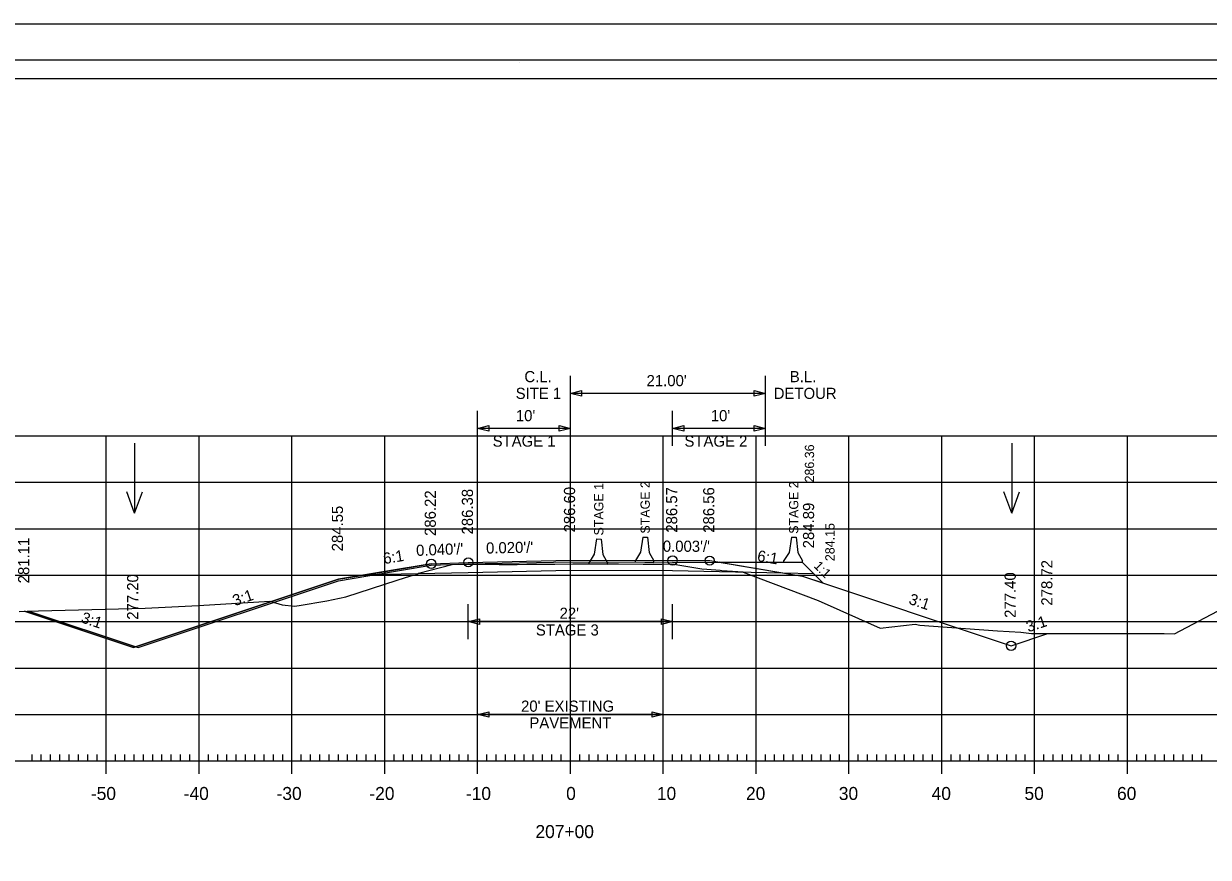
# Model space of a CAD drawing. Extents: x 1368713 to 1370673, y 380279 to 380950.
# Drawn here: x 1370450.7 to 1370578.3, y 380647.4 to 380737.1 of the extents above; entities that cross this region are included whole.
import ezdxf

# ---------------------------------------------------------------- set-up
doc = ezdxf.new("R2010")
doc.units = 0
for name, color, linetype in [('R_Alt Surface', 7, 'Continuous'), ('R_Axis', 7, 'Continuous'), ('R_Axis Annot', 7, 'Continuous'), ('R_Border', 7, 'Continuous'), ('R_CONC BARRIER', 7, 'Continuous'), ('R_Exist Surface', 7, 'Continuous'), ('R_Fin Surface', 7, 'Continuous'), ('R_Grid', 7, 'Continuous'), ('R_No Plot', 7, 'Continuous'), ('R_ROW Annot', 7, 'Continuous'), ('R_Stage 3 EW', 7, 'Continuous'), ('R_Water Annot', 7, 'Continuous'), ('R_Xsect Elev', 7, 'Continuous'), ('R_Xsect Slope', 7, 'Continuous')]:
    doc.layers.add(name, color=color, linetype=linetype)

msp = doc.modelspace()

# ---------------------------------------------------------------- linework, layer by layer
at = {"layer": 'R_Alt Surface'}
msp.add_line((1370532.48, 380678), (1370535.81, 380677.93), dxfattribs=at)
for points in [[(1370451.29, 380673.88), (1370463.07, 380669.95), (1370484.63, 380677.14), (1370487.79, 380677.67), (1370494.63, 380678.81), (1370498.63, 380678.97), (1370509.63, 380679.19), (1370520.63, 380679.15), (1370534.63, 380679.11), (1370535.98, 380677.76), (1370536.83, 380676.91)], [(1370494.63, 380678.97), (1370484.63, 380677.31)], [(1370524.63, 380679.31), (1370534.63, 380677.64)], [(1370487.79, 380677.83), (1370498.63, 380678.05), (1370509.63, 380678.27), (1370520.63, 380678.24), (1370532.48, 380678)], [(1370484.63, 380677.31), (1370462.57, 380669.95)], [(1370534.63, 380677.64), (1370557.1, 380670.15)], [(1370462.57, 380669.95), (1370462.57, 380669.95), (1370450.83, 380673.87)], [(1370557.1, 380670.15), (1370557.1, 380670.15), (1370561.05, 380671.47)]]:
    msp.add_lwpolyline(points, dxfattribs=at)
at = {"layer": 'R_Axis'}
for p, q in [((1370459.63, 380656.35), (1370459.63, 380659.15)), ((1370469.63, 380656.35), (1370469.63, 380659.15)), ((1370479.63, 380656.35), (1370479.63, 380659.15)), ((1370489.63, 380656.35), (1370489.63, 380659.15)), ((1370499.63, 380656.35), (1370499.63, 380659.15)), ((1370509.63, 380656.35), (1370509.63, 380659.15)), ((1370519.63, 380656.35), (1370519.63, 380659.15)), ((1370529.63, 380656.35), (1370529.63, 380659.15)), ((1370539.63, 380656.35), (1370539.63, 380659.15)), ((1370549.63, 380656.35), (1370549.63, 380659.15)), ((1370559.63, 380656.35), (1370559.63, 380659.15)), ((1370569.63, 380656.35), (1370569.63, 380659.15)), ((1370369.63, 380657.75), (1370649.63, 380657.75)), ((1370451.63, 380657.75), (1370451.63, 380658.45)), ((1370452.63, 380657.75), (1370452.63, 380658.45)), ((1370453.63, 380657.75), (1370453.63, 380658.45)), ((1370454.63, 380657.75), (1370454.63, 380658.45)), ((1370455.63, 380657.75), (1370455.63, 380658.45)), ((1370456.63, 380657.75), (1370456.63, 380658.45)), ((1370457.63, 380657.75), (1370457.63, 380658.45)), ((1370458.63, 380657.75), (1370458.63, 380658.45)), ((1370460.63, 380657.75), (1370460.63, 380658.45)), ((1370461.63, 380657.75), (1370461.63, 380658.45)), ((1370462.63, 380657.75), (1370462.63, 380658.45)), ((1370463.63, 380657.75), (1370463.63, 380658.45)), ((1370464.63, 380657.75), (1370464.63, 380658.45)), ((1370465.63, 380657.75), (1370465.63, 380658.45)), ((1370466.63, 380657.75), (1370466.63, 380658.45)), ((1370467.63, 380657.75), (1370467.63, 380658.45)), ((1370468.63, 380657.75), (1370468.63, 380658.45)), ((1370470.63, 380657.75), (1370470.63, 380658.45)), ((1370471.63, 380657.75), (1370471.63, 380658.45)), ((1370472.63, 380657.75), (1370472.63, 380658.45)), ((1370473.63, 380657.75), (1370473.63, 380658.45)), ((1370474.63, 380657.75), (1370474.63, 380658.45)), ((1370475.63, 380657.75), (1370475.63, 380658.45)), ((1370476.63, 380657.75), (1370476.63, 380658.45)), ((1370477.63, 380657.75), (1370477.63, 380658.45)), ((1370478.63, 380657.75), (1370478.63, 380658.45)), ((1370480.63, 380657.75), (1370480.63, 380658.45)), ((1370481.63, 380657.75), (1370481.63, 380658.45)), ((1370482.63, 380657.75), (1370482.63, 380658.45)), ((1370483.63, 380657.75), (1370483.63, 380658.45)), ((1370484.63, 380657.75), (1370484.63, 380658.45)), ((1370485.63, 380657.75), (1370485.63, 380658.45)), ((1370486.63, 380657.75), (1370486.63, 380658.45)), ((1370487.63, 380657.75), (1370487.63, 380658.45)), ((1370488.63, 380657.75), (1370488.63, 380658.45)), ((1370490.63, 380657.75), (1370490.63, 380658.45)), ((1370491.63, 380657.75), (1370491.63, 380658.45)), ((1370492.63, 380657.75), (1370492.63, 380658.45)), ((1370493.63, 380657.75), (1370493.63, 380658.45)), ((1370494.63, 380657.75), (1370494.63, 380658.45)), ((1370495.63, 380657.75), (1370495.63, 380658.45)), ((1370496.63, 380657.75), (1370496.63, 380658.45)), ((1370497.63, 380657.75), (1370497.63, 380658.45)), ((1370498.63, 380657.75), (1370498.63, 380658.45)), ((1370500.63, 380657.75), (1370500.63, 380658.45)), ((1370501.63, 380657.75), (1370501.63, 380658.45)), ((1370502.63, 380657.75), (1370502.63, 380658.45)), ((1370503.63, 380657.75), (1370503.63, 380658.45)), ((1370504.63, 380657.75), (1370504.63, 380658.45)), ((1370505.63, 380657.75), (1370505.63, 380658.45)), ((1370506.63, 380657.75), (1370506.63, 380658.45)), ((1370507.63, 380657.75), (1370507.63, 380658.45)), ((1370508.63, 380657.75), (1370508.63, 380658.45)), ((1370510.63, 380657.75), (1370510.63, 380658.45)), ((1370511.63, 380657.75), (1370511.63, 380658.45)), ((1370512.63, 380657.75), (1370512.63, 380658.45)), ((1370513.63, 380657.75), (1370513.63, 380658.45)), ((1370514.63, 380657.75), (1370514.63, 380658.45)), ((1370515.63, 380657.75), (1370515.63, 380658.45)), ((1370516.63, 380657.75), (1370516.63, 380658.45)), ((1370517.63, 380657.75), (1370517.63, 380658.45)), ((1370518.63, 380657.75), (1370518.63, 380658.45)), ((1370520.63, 380657.75), (1370520.63, 380658.45)), ((1370521.63, 380657.75), (1370521.63, 380658.45)), ((1370522.63, 380657.75), (1370522.63, 380658.45)), ((1370523.63, 380657.75), (1370523.63, 380658.45)), ((1370524.63, 380657.75), (1370524.63, 380658.45)), ((1370525.63, 380657.75), (1370525.63, 380658.45)), ((1370526.63, 380657.75), (1370526.63, 380658.45)), ((1370527.63, 380657.75), (1370527.63, 380658.45)), ((1370528.63, 380657.75), (1370528.63, 380658.45)), ((1370530.63, 380657.75), (1370530.63, 380658.45)), ((1370531.63, 380657.75), (1370531.63, 380658.45)), ((1370532.63, 380657.75), (1370532.63, 380658.45)), ((1370533.63, 380657.75), (1370533.63, 380658.45)), ((1370534.63, 380657.75), (1370534.63, 380658.45)), ((1370535.63, 380657.75), (1370535.63, 380658.45)), ((1370536.63, 380657.75), (1370536.63, 380658.45)), ((1370537.63, 380657.75), (1370537.63, 380658.45)), ((1370538.63, 380657.75), (1370538.63, 380658.45)), ((1370540.63, 380657.75), (1370540.63, 380658.45)), ((1370541.63, 380657.75), (1370541.63, 380658.45)), ((1370542.63, 380657.75), (1370542.63, 380658.45)), ((1370543.63, 380657.75), (1370543.63, 380658.45)), ((1370544.63, 380657.75), (1370544.63, 380658.45)), ((1370545.63, 380657.75), (1370545.63, 380658.45)), ((1370546.63, 380657.75), (1370546.63, 380658.45)), ((1370547.63, 380657.75), (1370547.63, 380658.45)), ((1370548.63, 380657.75), (1370548.63, 380658.45)), ((1370550.63, 380657.75), (1370550.63, 380658.45)), ((1370551.63, 380657.75), (1370551.63, 380658.45)), ((1370552.63, 380657.75), (1370552.63, 380658.45)), ((1370553.63, 380657.75), (1370553.63, 380658.45)), ((1370554.63, 380657.75), (1370554.63, 380658.45)), ((1370555.63, 380657.75), (1370555.63, 380658.45)), ((1370556.63, 380657.75), (1370556.63, 380658.45)), ((1370557.63, 380657.75), (1370557.63, 380658.45)), ((1370558.63, 380657.75), (1370558.63, 380658.45)), ((1370560.63, 380657.75), (1370560.63, 380658.45)), ((1370561.63, 380657.75), (1370561.63, 380658.45)), ((1370562.63, 380657.75), (1370562.63, 380658.45)), ((1370563.63, 380657.75), (1370563.63, 380658.45)), ((1370564.63, 380657.75), (1370564.63, 380658.45)), ((1370565.63, 380657.75), (1370565.63, 380658.45)), ((1370566.63, 380657.75), (1370566.63, 380658.45)), ((1370567.63, 380657.75), (1370567.63, 380658.45)), ((1370568.63, 380657.75), (1370568.63, 380658.45)), ((1370570.63, 380657.75), (1370570.63, 380658.45)), ((1370571.63, 380657.75), (1370571.63, 380658.45)), ((1370572.63, 380657.75), (1370572.63, 380658.45)), ((1370573.63, 380657.75), (1370573.63, 380658.45)), ((1370574.63, 380657.75), (1370574.63, 380658.45)), ((1370575.63, 380657.75), (1370575.63, 380658.45)), ((1370576.63, 380657.75), (1370576.63, 380658.45)), ((1370577.63, 380657.75), (1370577.63, 380658.45))]:
    msp.add_line(p, q, dxfattribs=at)
at = {"layer": 'R_Border'}
for p, q in [((1370351.63, 380733.21), (1370667.81, 380733.21)), ((1370504.15, 380732.95), (1370504.15, 380732.95)), ((1370504.15, 380732.95), (1370504.15, 380732.95))]:
    msp.add_line(p, q, dxfattribs=at)
at = {"layer": 'R_CONC BARRIER'}
for p, q in [((1370512.43, 380681.65), (1370512.93, 380681.64)), ((1370517.43, 380681.85), (1370517.93, 380681.84)), ((1370533.43, 380681.84), (1370533.93, 380681.83)), ((1370511.63, 380678.97), (1370511.63, 380679.13)), ((1370511.63, 380678.97), (1370513.63, 380678.93)), ((1370513.63, 380678.93), (1370513.63, 380679.09)), ((1370516.63, 380679.17), (1370516.63, 380679.33)), ((1370516.63, 380679.17), (1370518.63, 380679.13)), ((1370518.63, 380679.13), (1370518.63, 380679.29)), ((1370532.63, 380679.15), (1370532.63, 380679.32)), ((1370532.63, 380679.15), (1370534.63, 380679.11)), ((1370534.63, 380679.11), (1370534.63, 380679.28))]:
    msp.add_line(p, q, dxfattribs=at)
for points in [[(1370512.43, 380681.65), (1370512.18, 380680.01), (1370511.63, 380679.13)], [(1370512.93, 380681.64), (1370513.12, 380679.99), (1370513.63, 380679.09)], [(1370517.43, 380681.85), (1370517.18, 380680.21), (1370516.63, 380679.33)], [(1370517.93, 380681.84), (1370518.12, 380680.19), (1370518.63, 380679.29)], [(1370533.43, 380681.84), (1370533.18, 380680.2), (1370532.63, 380679.32)], [(1370533.93, 380681.83), (1370534.12, 380680.18), (1370534.63, 380679.28)]]:
    msp.add_lwpolyline(points, dxfattribs=at)
at = {"layer": 'R_Exist Surface'}
msp.add_lwpolyline([(1370450.25, 380673.85), (1370451.1, 380673.87), (1370452.33, 380673.91), (1370463.81, 380674.18), (1370469.57, 380674.47), (1370477.24, 380674.96), (1370478.56, 380674.57), (1370479.91, 380674.42), (1370480.4, 380674.48), (1370483.39, 380674.97), (1370485.42, 380675.42), (1370490.97, 380677.2), (1370492.42, 380677.68), (1370493.08, 380677.83), (1370493.28, 380677.95), (1370496.88, 380678.91), (1370499.66, 380678.93), (1370501.94, 380678.88), (1370503.88, 380678.9), (1370504.95, 380678.92), (1370506.88, 380678.95), (1370507.95, 380678.95), (1370509.88, 380678.96), (1370510.95, 380678.96), (1370512.88, 380678.97), (1370514.79, 380678.97), (1370517.48, 380678.94), (1370519.48, 380678.95), (1370520.56, 380678.96), (1370523.8, 380678.42), (1370524.33, 380678.39), (1370525.77, 380678.29), (1370525.95, 380678.24), (1370528.22, 380678.09), (1370528.24, 380678.08), (1370536.33, 380675.02), (1370542.99, 380672.04), (1370546.75, 380672.48), (1370547.27, 380672.36), (1370555.63, 380671.74), (1370558.15, 380671.63), (1370559.31, 380671.47), (1370565.36, 380671.47), (1370573.58, 380671.47), (1370574.72, 380671.42), (1370580.02, 380674.23)], dxfattribs=at)
at = {"layer": 'R_Fin Surface'}
for points in [[(1370450.83, 380673.87), (1370462.57, 380669.95), (1370484.63, 380677.31), (1370487.79, 380677.83), (1370494.63, 380678.97), (1370498.63, 380679.13), (1370509.63, 380679.35), (1370520.63, 380679.32), (1370524.63, 380679.31), (1370532.48, 380678), (1370534.63, 380677.64), (1370557.1, 380670.15), (1370561.05, 380671.47)], [(1370494.63, 380678.97), (1370498.63, 380679.13), (1370509.63, 380679.35), (1370520.63, 380679.32), (1370524.63, 380679.31)]]:
    msp.add_lwpolyline(points, dxfattribs=at)
at = {"layer": 'R_Grid'}
for p, q in [((1370369.63, 380692.75), (1370649.63, 380692.75)), ((1370459.63, 380657.75), (1370459.63, 380692.75)), ((1370469.63, 380657.75), (1370469.63, 380692.75)), ((1370479.63, 380657.75), (1370479.63, 380692.75)), ((1370489.63, 380657.75), (1370489.63, 380692.75)), ((1370499.63, 380657.75), (1370499.63, 380692.75)), ((1370509.63, 380657.75), (1370509.63, 380692.75)), ((1370519.63, 380657.75), (1370519.63, 380692.75)), ((1370529.63, 380657.75), (1370529.63, 380692.75)), ((1370539.63, 380657.75), (1370539.63, 380692.75)), ((1370549.63, 380657.75), (1370549.63, 380692.75)), ((1370559.63, 380657.75), (1370559.63, 380692.75)), ((1370569.63, 380657.75), (1370569.63, 380692.75)), ((1370369.63, 380687.75), (1370649.63, 380687.75)), ((1370369.63, 380682.75), (1370649.63, 380682.75)), ((1370369.63, 380677.75), (1370649.63, 380677.75)), ((1370369.63, 380672.75), (1370649.63, 380672.75)), ((1370369.63, 380667.75), (1370649.63, 380667.75)), ((1370369.63, 380662.75), (1370649.63, 380662.75)), ((1370369.63, 380657.75), (1370649.63, 380657.75))]:
    msp.add_line(p, q, dxfattribs=at)
at = {"layer": 'R_No Plot'}
for points in [[(1370339.22, 380737.11), (1370672.56, 380737.11), (1370672.56, 380523.77), (1370339.22, 380523.77)], [(1370665.81, 380632.48), (1370353.63, 380632.48), (1370353.63, 380731.21), (1370603.17, 380731.21), (1370603.17, 380721.33), (1370620.71, 380721.33), (1370644.81, 380721.33), (1370644.81, 380699), (1370665.81, 380699)], [(1370353.63, 380731.21), (1370603.17, 380731.21), (1370603.17, 380721.33), (1370620.71, 380721.33), (1370644.81, 380721.33), (1370644.81, 380699), (1370665.81, 380699), (1370665.81, 380529.75), (1370353.63, 380529.75)]]:
    msp.add_lwpolyline(points, close=True, dxfattribs=at)
for centre in [(1370494.63, 380678.97), (1370494.63, 380678.97), (1370498.63, 380679.13), (1370498.63, 380679.13), (1370520.63, 380679.32), (1370520.63, 380679.32), (1370524.63, 380679.31), (1370524.63, 380679.31), (1370557.1, 380670.15), (1370557.1, 380670.15)]:
    msp.add_circle(centre, 0.5, dxfattribs=at)
at = {"layer": 'R_ROW Annot'}
for p, q in [((1370509.63, 380695.44), (1370509.63, 380699.21)), ((1370530.63, 380695.44), (1370530.63, 380699.21)), ((1370530.63, 380697.32), (1370509.63, 380697.32)), ((1370499.63, 380691.67), (1370499.63, 380695.44)), ((1370509.63, 380691.67), (1370509.63, 380695.44)), ((1370520.63, 380691.67), (1370520.63, 380695.44)), ((1370530.63, 380691.67), (1370530.63, 380695.44)), ((1370509.63, 380693.55), (1370499.63, 380693.55)), ((1370530.63, 380693.55), (1370520.63, 380693.55)), ((1370498.63, 380670.87), (1370498.63, 380674.64)), ((1370520.63, 380670.87), (1370520.63, 380674.64)), ((1370520.63, 380672.75), (1370498.63, 380672.75)), ((1370499.63, 380660.87), (1370499.63, 380664.64)), ((1370519.63, 380660.87), (1370519.63, 380664.64)), ((1370519.63, 380662.75), (1370499.63, 380662.75))]:
    msp.add_line(p, q, dxfattribs=at)
for points in [[(1370510.83, 380697.02), (1370509.63, 380697.32), (1370510.83, 380697.62)], [(1370529.43, 380697.62), (1370530.63, 380697.32), (1370529.43, 380697.02)], [(1370500.83, 380693.25), (1370499.63, 380693.55), (1370500.83, 380693.85)], [(1370508.43, 380693.85), (1370509.63, 380693.55), (1370508.43, 380693.25)], [(1370521.83, 380693.25), (1370520.63, 380693.55), (1370521.83, 380693.85)], [(1370529.43, 380693.85), (1370530.63, 380693.55), (1370529.43, 380693.25)], [(1370499.83, 380672.45), (1370498.63, 380672.75), (1370499.83, 380673.05)], [(1370519.43, 380673.05), (1370520.63, 380672.75), (1370519.43, 380672.45)], [(1370500.83, 380662.45), (1370499.63, 380662.75), (1370500.83, 380663.05)], [(1370518.43, 380663.05), (1370519.63, 380662.75), (1370518.43, 380662.45)]]:
    msp.add_lwpolyline(points, close=True, dxfattribs=at)
at = {"layer": 'R_Stage 3 EW'}
for p, q in [((1370534.63, 380679.11), (1370525.65, 380679.14)), ((1370525.65, 380679.14), (1370532.48, 380678)), ((1370536.83, 380676.91), (1370534.63, 380679.11)), ((1370532.48, 380678), (1370534.63, 380677.64)), ((1370534.63, 380677.64), (1370536.83, 380676.91))]:
    msp.add_line(p, q, dxfattribs=at)
at = {"layer": 'R_Water Annot'}
for p, q in [((1370462.68, 380691.95), (1370462.68, 380684.41)), ((1370557.17, 380691.95), (1370557.17, 380684.41)), ((1370462.68, 380684.41), (1370461.84, 380686.72)), ((1370462.68, 380684.41), (1370463.52, 380686.72)), ((1370557.17, 380684.41), (1370556.33, 380686.72)), ((1370557.17, 380684.41), (1370558.01, 380686.72))]:
    msp.add_line(p, q, dxfattribs=at)

# ---------------------------------------------------------------- texts
at = {"layer": 'R_Axis Annot'}
for s, p in [('-50', (1370457.97, 380653.55)), ('-40', (1370467.97, 380653.55)), ('-30', (1370477.97, 380653.55)), ('-20', (1370487.97, 380653.55)), ('-10', (1370498.37, 380653.55)), ('0', (1370509.17, 380653.55)), ('10', (1370518.94, 380653.55)), ('20', (1370528.54, 380653.55)), ('30', (1370538.54, 380653.55)), ('40', (1370548.54, 380653.55)), ('50', (1370558.54, 380653.55)), ('60', (1370568.51, 380653.55)), ('207+00', (1370505.86, 380649.45))]:
    msp.add_text(s, height=1.4, dxfattribs=at).set_placement(p)
at = {"layer": 'R_CONC BARRIER'}
for s, p in [(' STAGE 1', (1370513.18, 380681.65)), (' STAGE 2', (1370518.18, 380681.85)), (' STAGE 2', (1370534.18, 380681.83))]:
    msp.add_text(s, height=1, rotation=90, dxfattribs=at).set_placement(p)
at = {"layer": 'R_ROW Annot'}
for s, p in [('C.L.', (1370504.67, 380698.52)), ('B.L.', (1370533.26, 380698.52)), ("21.00'", (1370517.83, 380698.09)), ('SITE 1', (1370503.73, 380696.72)), ('DETOUR', (1370531.53, 380696.72)), ("10'", (1370503.75, 380694.32)), ("10'", (1370524.75, 380694.32)), ('STAGE 1', (1370501.25, 380691.58)), ('STAGE 2', (1370521.91, 380691.58)), ("22'", (1370508.46, 380673.05)), ('STAGE 3', (1370505.91, 380671.25)), ("20' EXISTING", (1370504.31, 380663.05)), ('PAVEMENT', (1370505.21, 380661.25))]:
    msp.add_text(s, height=1.2, dxfattribs=at).set_placement(p)
at = {"layer": 'R_Xsect Elev'}
for s, height, p in [('286.36', 1, (1370535.88, 380687.73)), ('286.22', 1.2, (1370495.13, 380681.97)), ('286.38', 1.2, (1370499.13, 380682.13)), ('286.60', 1.2, (1370510.13, 380682.35)), ('286.57', 1.2, (1370521.13, 380682.32)), ('286.56', 1.2, (1370525.13, 380682.31)), ('284.89', 1.2, (1370535.88, 380680.64)), ('284.55', 1.2, (1370485.13, 380680.31)), ('284.15', 1, (1370538.08, 380679.26)), ('281.11', 1.2, (1370451.33, 380676.87)), ('278.72', 1.2, (1370561.55, 380674.47)), ('277.20', 1.2, (1370463.07, 380672.95)), ('277.40', 1.2, (1370557.6, 380673.15))]:
    msp.add_text(s, height=height, rotation=90, dxfattribs=at).set_placement(p)
at = {"layer": 'R_Xsect Slope'}
for s, height, rotation, p in [("0.003'/'", 1.2, 359.8306, (1370519.58, 380680.27)), ('6:1', 1.2, 9.4623, (1370489.56, 380678.93)), ("0.040'/'", 1.2, 2.2906, (1370493.03, 380679.81)), ("0.020'/'", 1.2, 1.1458, (1370500.55, 380680.07)), ('6:1', 1.2, 350.5377, (1370529.69, 380679.27)), ('1:1', 1, 315, (1370535.78, 380678.67)), ('3:1', 1.2, 18.4349, (1370473.47, 380674.41)), ('3:1', 1.2, 341.5651, (1370545.99, 380674.68)), ('3:1', 1.2, 341.5651, (1370456.83, 380672.69)), ('3:1', 1.2, 18.4349, (1370558.95, 380671.59))]:
    msp.add_text(s, height=height, rotation=rotation, dxfattribs=at).set_placement(p)

doc.saveas('drawing.dxf')
